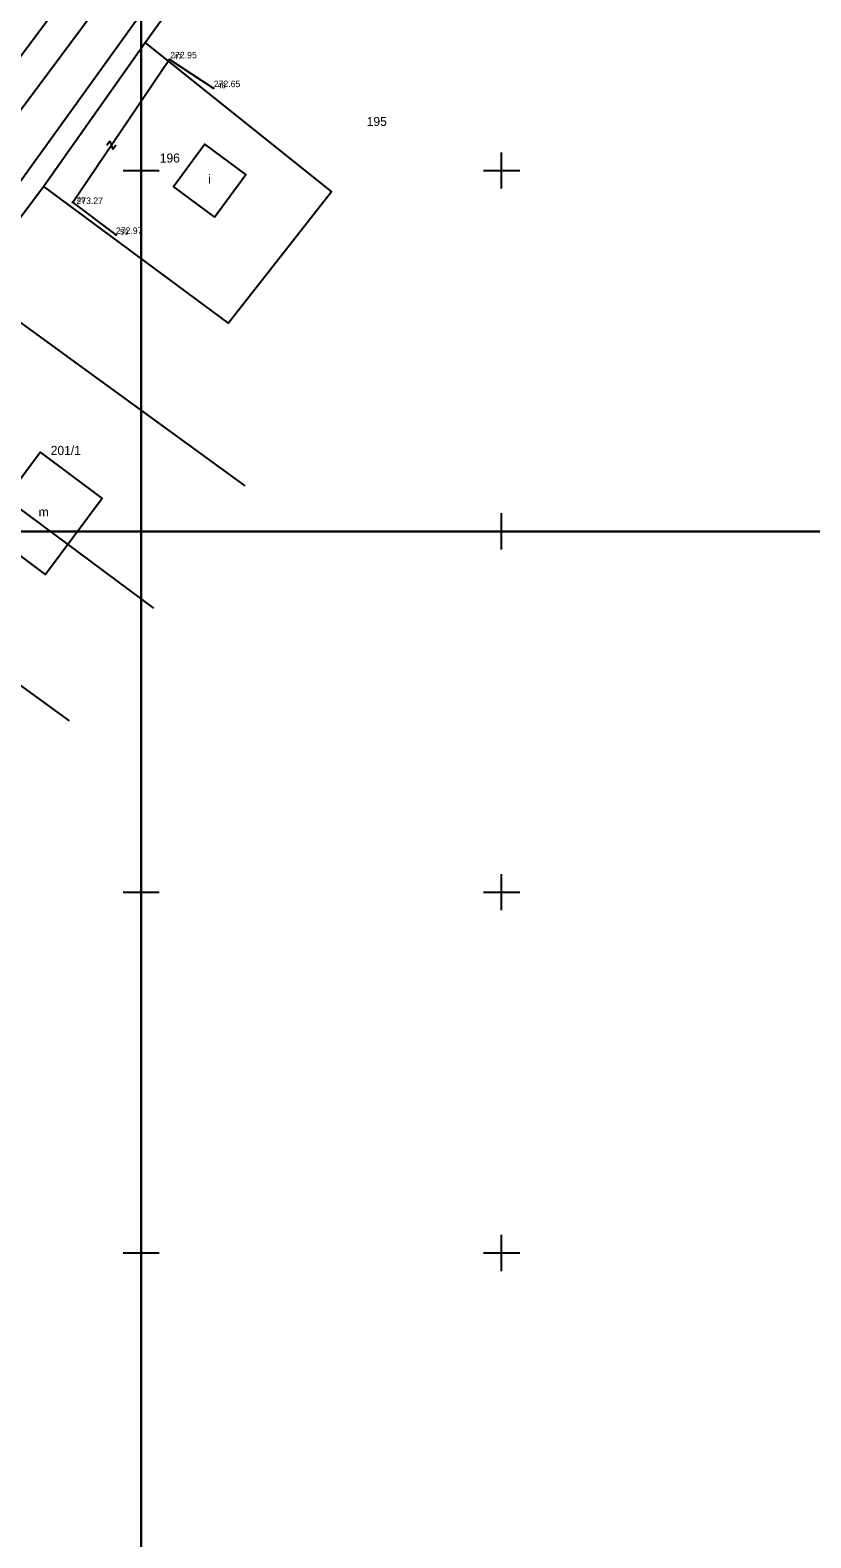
# Model space of a CAD drawing. Extents: x 4632591 to 4653165, y 5351032 to 5369868.
# Drawn here: x 4647984.6 to 4648092.9, y 5364110.5 to 5364319.5 of the extents above; entities that cross this region are included whole.
import ezdxf

# ---------------------------------------------------------------- set-up
doc = ezdxf.new("R2010")
doc.units = 0
for name, color, linetype in [('EBUPP_316', 7, 'Continuous'), ('EDTTS_991', 7, 'Continuous'), ('EDZPD_211', 7, 'Continuous'), ('EDZPD_219', 7, 'Continuous'), ('SDRPK_420', 7, 'Continuous'), ('SZOPO_902', 7, 'Continuous'), ('Warstwa 60', 7, 'Continuous'), ('Warstwa 62', 7, 'Continuous'), ('WUKPS_403', 7, 'Continuous')]:
    doc.layers.add(name, color=color, linetype=linetype)

msp = doc.modelspace()

# ---------------------------------------------------------------- linework, layer by layer
at = {"layer": 'EBUPP_316'}
for points in [[(4648010.19, 5364293.55), (4648014.53, 5364299.44), (4648008.83, 5364303.64), (4648004.49, 5364297.75)], [(4647978.12, 5364250.45), (4647985.98, 5364260.97), (4647994.6, 5364254.54), (4647986.74, 5364244.01)]]:
    msp.add_lwpolyline(points, close=True, dxfattribs=at)
at = {"layer": 'EDTTS_991'}
for p, q in [((4647995.68, 5364304.08), (4647995.26, 5364303.46)), ((4647995.68, 5364304.08), (4647996.09, 5364302.9)), ((4647996.51, 5364303.52), (4647996.09, 5364302.9))]:
    msp.add_line(p, q, dxfattribs=at)
at = {"layer": 'EDZPD_219'}
for points in [[(4648000.57, 5364317.76), (4648034.21, 5364364.32), (4648040.2, 5364369.58), (4648048.82, 5364374.2)], [(4647962.73, 5364288.39), (4648002.96, 5364342.24)], [(4647986.46, 5364297.77), (4648000.57, 5364317.76)], [(4647986.46, 5364297.77), (4648012.09, 5364278.83), (4648026.4, 5364297.07), (4648000.57, 5364317.76)], [(4647976.14, 5364284.07), (4647986.46, 5364297.77)], [(4647976.14, 5364284.07), (4648014.4, 5364256.3)], [(4647963.86, 5364267.44), (4648001.71, 5364239.35)], [(4647951.97, 5364251.34), (4647990.03, 5364223.74)]]:
    msp.add_lwpolyline(points, dxfattribs=at)
at = {"layer": 'SDRPK_420'}
for points in [[(4648092.72, 5364381.83), (4648082.62, 5364381.46), (4648055.55, 5364380.64), (4648043.07, 5364377.86), (4648027.67, 5364366), (4648008.86, 5364342.67), (4647965.85, 5364285.01), (4647944.7, 5364256.84), (4647902.04, 5364201.17), (4647856.51, 5364140.83), (4647809.31, 5364078.36), (4647805.24, 5364072.69), (4647784.46, 5364045.15), (4647745.1, 5363992.73)], [(4648092.72, 5364376.04), (4648077.88, 5364375.54), (4648055.17, 5364374.72), (4648045.43, 5364372.58), (4648031.31, 5364362.68), (4648012.8, 5364339.82), (4648008.57, 5364333.61), (4647979.04, 5364292.64), (4647969.71, 5364281.94), (4647966.12, 5364277.23), (4647948.54, 5364254.19), (4647905.81, 5364197.94), (4647860.39, 5364138.03), (4647846.02, 5364119.01), (4647812.96, 5364075.36), (4647788.26, 5364042.12), (4647755.52, 5363998.94)]]:
    msp.add_lwpolyline(points, dxfattribs=at)
at = {"layer": 'SZOPO_902'}
msp.add_lwpolyline([(4648010.01, 5364311.4), (4648003.96, 5364315.4), (4647990.53, 5364295.59), (4647996.51, 5364291.09)], dxfattribs=at)
at = {"layer": 'Warstwa 60'}
for p, q in [((4648050, 5364297.5), (4648050, 5364302.5)), ((4647997.5, 5364300), (4648000, 5364300)), ((4648000, 5364300), (4648002.5, 5364300)), ((4648047.5, 5364300), (4648052.5, 5364300)), ((4648050, 5364250), (4648050, 5364252.5)), ((4648050, 5364247.5), (4648050, 5364250)), ((4648050, 5364197.5), (4648050, 5364202.5)), ((4647997.5, 5364200), (4648000, 5364200)), ((4648000, 5364200), (4648002.5, 5364200)), ((4648047.5, 5364200), (4648052.5, 5364200)), ((4648050, 5364147.5), (4648050, 5364152.5)), ((4647997.5, 5364150), (4648000, 5364150)), ((4648000, 5364150), (4648002.5, 5364150)), ((4648047.5, 5364150), (4648052.5, 5364150))]:
    msp.add_line(p, q, dxfattribs=at)
for points in [[(4647600, 5364250), (4647600, 5364500), (4648000, 5364500), (4648000, 5364250)], [(4648000, 5364250), (4648000, 5364500), (4648400, 5364500), (4648400, 5364250)], [(4647600, 5364000), (4647600, 5364250), (4648000, 5364250), (4648000, 5364000)], [(4648000, 5364000), (4648000, 5364250), (4648400, 5364250), (4648400, 5364000)]]:
    msp.add_lwpolyline(points, close=True, dxfattribs=at)
at = {"layer": 'WUKPS_403'}
for centre in [(4648003.96, 5364315.39), (4648010.01, 5364311.4), (4647990.53, 5364295.59), (4647996.51, 5364291.09)]:
    msp.add_circle(centre, 0.045, dxfattribs=at)

# ---------------------------------------------------------------- texts
at = {"layer": 'EBUPP_316'}
for s, p in [('i', (4648009.31, 5364298.2)), ('m', (4647985.79, 5364252.06))]:
    msp.add_text(s, height=1.25, dxfattribs=at).set_placement(p)
at = {"layer": 'EDZPD_211'}
for s, p in [('195', (4648031.29, 5364306.17)), ('196', (4648002.59, 5364301.11)), ('201/1', (4647987.46, 5364260.59))]:
    msp.add_text(s, height=1.25, dxfattribs=at).set_placement(p)
at = {"layer": 'Warstwa 62'}
for s, p in [('. 47', (4648003.96, 5364315.4)), ('. 48', (4648010.01, 5364311.4)), ('. 49', (4647990.53, 5364295.59)), ('. 50', (4647996.51, 5364291.09))]:
    msp.add_text(s, height=0.75, dxfattribs=at).set_placement(p)
at = {"layer": 'WUKPS_403'}
for s, p in [('272.95', (4648004.04, 5364315.54)), ('272.65', (4648010.08, 5364311.55)), ('273.27', (4647991.03, 5364295.36)), ('272.97', (4647996.51, 5364291.22))]:
    msp.add_text(s, height=0.9, dxfattribs=at).set_placement(p)

doc.saveas('drawing.dxf')
